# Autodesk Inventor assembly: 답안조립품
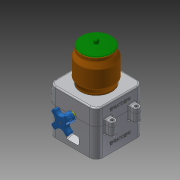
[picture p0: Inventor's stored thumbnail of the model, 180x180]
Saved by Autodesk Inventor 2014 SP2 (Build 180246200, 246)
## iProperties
Created: 2018-01
Part Number: 답안조립품
Document SubType Name: Assembly
Designer: 거성
Author: 거성
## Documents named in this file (9)
- C:\Users\거성\Desktop\480108V1015\답안조립품.iam
- C:\Users\거성\Desktop\480108V1015\본체.ipt
- C:\Users\거성\Desktop\480108V1015\핸들축.ipt
- C:\Users\거성\Desktop\480108V1015\볼트 M3x12.ipt
- C:\Users\거성\Desktop\480108V1015\핸들.ipt
- C:\Users\거성\Desktop\480108V1015\본체커버.ipt
- C:\Users\거성\Desktop\480108V1015\용기.ipt
- C:\Users\거성\Desktop\480108V1015\용기캡.ipt
- C:\Users\거성\Desktop\480108V1015\볼트 M4x12.ipt
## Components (2 placed, 2 different names)
1. 핸들축:1 — 각도:1
2. 핸들:1 — 각도:1
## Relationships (1: Angle 1)
- 각도:1 [Angle]: 핸들축:1 ↔ 핸들:1
